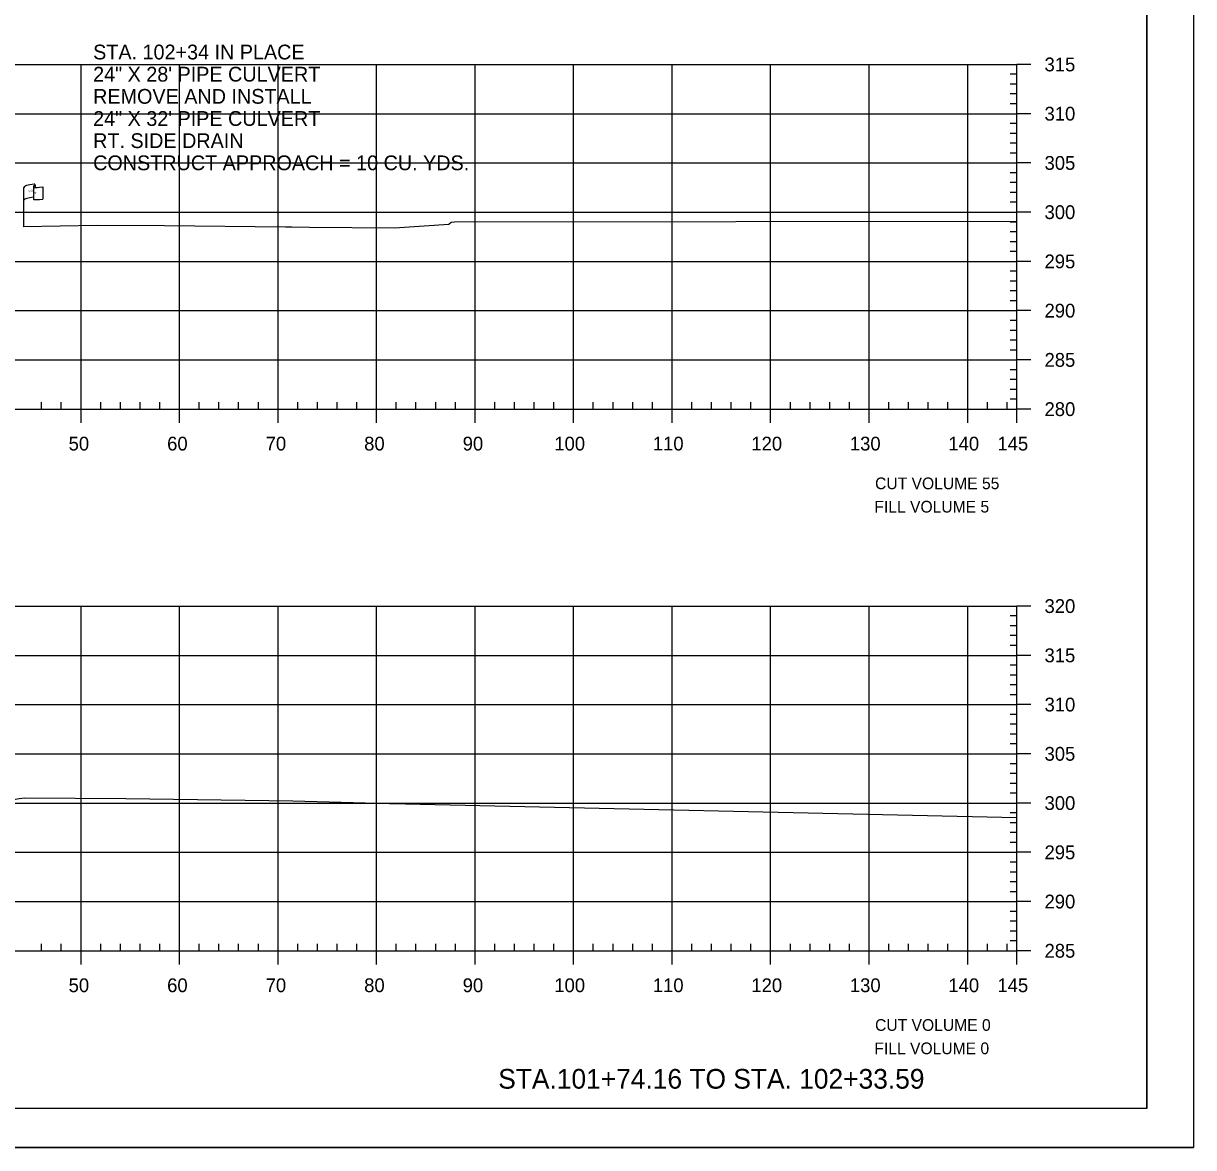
# Model space of a CAD drawing. Extents: x 1370843 to 1371177, y 380307 to 382654.
# Drawn here: x 1371057.9 to 1371176.6, y 380307.5 to 380421.6 of the extents above; entities that cross this region are included whole.
import ezdxf

# ---------------------------------------------------------------- set-up
doc = ezdxf.new("R2010")
doc.units = 0
for name, color, linetype in [('R_Axis', 7, 'Continuous'), ('R_Axis Annot', 7, 'Continuous'), ('R_Border', 7, 'Continuous'), ('R_Border Notes', 7, 'Continuous'), ('R_Draft', 7, 'Continuous'), ('R_Exist Surface', 7, 'Continuous'), ('R_Grid', 7, 'Continuous'), ('R_No Plot', 7, 'Continuous'), ('R_ROW', 7, 'Continuous'), ('R_Water Annot', 7, 'Continuous')]:
    doc.layers.add(name, color=color, linetype=linetype)

msp = doc.modelspace()

# ---------------------------------------------------------------- linework, layer by layer
at = {"layer": 'R_Axis'}
for p, q in [((1371158.71, 380382.45), (1371158.71, 380417.45)), ((1371160.11, 380417.45), (1371158.71, 380417.45)), ((1371158.71, 380416.45), (1371158.01, 380416.45)), ((1371158.71, 380415.45), (1371158.01, 380415.45)), ((1371158.71, 380414.45), (1371158.01, 380414.45)), ((1371158.71, 380413.45), (1371158.01, 380413.45)), ((1371160.11, 380412.45), (1371158.71, 380412.45)), ((1371158.71, 380411.45), (1371158.01, 380411.45)), ((1371158.71, 380410.45), (1371158.01, 380410.45)), ((1371158.71, 380409.45), (1371158.01, 380409.45)), ((1371158.71, 380408.45), (1371158.01, 380408.45)), ((1371160.11, 380407.45), (1371158.71, 380407.45)), ((1371158.71, 380406.45), (1371158.01, 380406.45)), ((1371158.71, 380405.45), (1371158.01, 380405.45)), ((1371158.71, 380404.45), (1371158.01, 380404.45)), ((1371158.71, 380403.45), (1371158.01, 380403.45)), ((1371160.11, 380402.45), (1371158.71, 380402.45)), ((1371158.71, 380401.45), (1371158.01, 380401.45)), ((1371158.71, 380400.45), (1371158.01, 380400.45)), ((1371158.71, 380399.45), (1371158.01, 380399.45)), ((1371158.71, 380398.45), (1371158.01, 380398.45)), ((1371160.11, 380397.45), (1371158.71, 380397.45)), ((1371158.71, 380396.45), (1371158.01, 380396.45)), ((1371158.71, 380395.45), (1371158.01, 380395.45)), ((1371158.71, 380394.45), (1371158.01, 380394.45)), ((1371158.71, 380393.45), (1371158.01, 380393.45)), ((1371160.11, 380392.45), (1371158.71, 380392.45)), ((1371158.71, 380391.45), (1371158.01, 380391.45)), ((1371158.71, 380390.45), (1371158.01, 380390.45)), ((1371158.71, 380389.45), (1371158.01, 380389.45)), ((1371158.71, 380388.45), (1371158.01, 380388.45)), ((1371160.11, 380387.45), (1371158.71, 380387.45)), ((1371158.71, 380386.45), (1371158.01, 380386.45)), ((1371158.71, 380385.45), (1371158.01, 380385.45)), ((1371158.71, 380384.45), (1371158.01, 380384.45)), ((1371059.71, 380382.45), (1371059.71, 380383.15)), ((1371061.71, 380382.45), (1371061.71, 380383.15)), ((1371065.71, 380382.45), (1371065.71, 380383.15)), ((1371067.71, 380382.45), (1371067.71, 380383.15)), ((1371069.71, 380382.45), (1371069.71, 380383.15)), ((1371071.71, 380382.45), (1371071.71, 380383.15)), ((1371075.71, 380382.45), (1371075.71, 380383.15)), ((1371077.71, 380382.45), (1371077.71, 380383.15)), ((1371079.71, 380382.45), (1371079.71, 380383.15)), ((1371081.71, 380382.45), (1371081.71, 380383.15)), ((1371085.71, 380382.45), (1371085.71, 380383.15)), ((1371087.71, 380382.45), (1371087.71, 380383.15)), ((1371089.71, 380382.45), (1371089.71, 380383.15)), ((1371091.71, 380382.45), (1371091.71, 380383.15)), ((1371095.71, 380382.45), (1371095.71, 380383.15)), ((1371097.71, 380382.45), (1371097.71, 380383.15)), ((1371099.71, 380382.45), (1371099.71, 380383.15)), ((1371101.71, 380382.45), (1371101.71, 380383.15)), ((1371105.71, 380382.45), (1371105.71, 380383.15)), ((1371107.71, 380382.45), (1371107.71, 380383.15)), ((1371109.71, 380382.45), (1371109.71, 380383.15)), ((1371111.71, 380382.45), (1371111.71, 380383.15)), ((1371115.71, 380382.45), (1371115.71, 380383.15)), ((1371117.71, 380382.45), (1371117.71, 380383.15)), ((1371119.71, 380382.45), (1371119.71, 380383.15)), ((1371121.71, 380382.45), (1371121.71, 380383.15)), ((1371125.71, 380382.45), (1371125.71, 380383.15)), ((1371127.71, 380382.45), (1371127.71, 380383.15)), ((1371129.71, 380382.45), (1371129.71, 380383.15)), ((1371131.71, 380382.45), (1371131.71, 380383.15)), ((1371135.71, 380382.45), (1371135.71, 380383.15)), ((1371137.71, 380382.45), (1371137.71, 380383.15)), ((1371139.71, 380382.45), (1371139.71, 380383.15)), ((1371141.71, 380382.45), (1371141.71, 380383.15)), ((1371145.71, 380382.45), (1371145.71, 380383.15)), ((1371147.71, 380382.45), (1371147.71, 380383.15)), ((1371149.71, 380382.45), (1371149.71, 380383.15)), ((1371151.71, 380382.45), (1371151.71, 380383.15)), ((1371155.71, 380382.45), (1371155.71, 380383.15)), ((1371157.71, 380382.45), (1371157.71, 380383.15)), ((1371158.71, 380383.45), (1371158.01, 380383.45)), ((1370868.71, 380382.45), (1371158.71, 380382.45)), ((1371063.71, 380381.05), (1371063.71, 380382.45)), ((1371073.71, 380381.05), (1371073.71, 380382.45)), ((1371083.71, 380381.05), (1371083.71, 380382.45)), ((1371093.71, 380381.05), (1371093.71, 380382.45)), ((1371103.71, 380381.05), (1371103.71, 380382.45)), ((1371113.71, 380381.05), (1371113.71, 380382.45)), ((1371123.71, 380381.05), (1371123.71, 380382.45)), ((1371133.71, 380381.05), (1371133.71, 380382.45)), ((1371143.71, 380381.05), (1371143.71, 380382.45)), ((1371153.71, 380381.05), (1371153.71, 380382.45)), ((1371158.71, 380381.05), (1371158.71, 380382.45)), ((1371160.11, 380382.45), (1371158.71, 380382.45)), ((1371158.71, 380327.45), (1371158.71, 380362.45)), ((1371160.11, 380362.45), (1371158.71, 380362.45)), ((1371158.71, 380361.45), (1371158.01, 380361.45)), ((1371158.71, 380360.45), (1371158.01, 380360.45)), ((1371158.71, 380359.45), (1371158.01, 380359.45)), ((1371158.71, 380358.45), (1371158.01, 380358.45)), ((1371160.11, 380357.45), (1371158.71, 380357.45)), ((1371158.71, 380356.45), (1371158.01, 380356.45)), ((1371158.71, 380355.45), (1371158.01, 380355.45)), ((1371158.71, 380354.45), (1371158.01, 380354.45)), ((1371158.71, 380353.45), (1371158.01, 380353.45)), ((1371160.11, 380352.45), (1371158.71, 380352.45)), ((1371158.71, 380351.45), (1371158.01, 380351.45)), ((1371158.71, 380350.45), (1371158.01, 380350.45)), ((1371158.71, 380349.45), (1371158.01, 380349.45)), ((1371158.71, 380348.45), (1371158.01, 380348.45)), ((1371160.11, 380347.45), (1371158.71, 380347.45)), ((1371158.71, 380346.45), (1371158.01, 380346.45)), ((1371158.71, 380345.45), (1371158.01, 380345.45)), ((1371158.71, 380344.45), (1371158.01, 380344.45)), ((1371158.71, 380343.45), (1371158.01, 380343.45)), ((1371158.71, 380341.45), (1371158.01, 380341.45)), ((1371160.11, 380342.45), (1371158.71, 380342.45)), ((1371158.71, 380340.45), (1371158.01, 380340.45)), ((1371158.71, 380339.45), (1371158.01, 380339.45)), ((1371158.71, 380338.45), (1371158.01, 380338.45)), ((1371160.11, 380337.45), (1371158.71, 380337.45)), ((1371158.71, 380336.45), (1371158.01, 380336.45)), ((1371158.71, 380335.45), (1371158.01, 380335.45)), ((1371158.71, 380334.45), (1371158.01, 380334.45)), ((1371158.71, 380333.45), (1371158.01, 380333.45)), ((1371160.11, 380332.45), (1371158.71, 380332.45)), ((1371158.71, 380331.45), (1371158.01, 380331.45)), ((1371158.71, 380330.45), (1371158.01, 380330.45)), ((1371158.71, 380329.45), (1371158.01, 380329.45)), ((1371158.71, 380328.45), (1371158.01, 380328.45)), ((1370868.71, 380327.45), (1371158.71, 380327.45)), ((1371059.71, 380327.45), (1371059.71, 380328.15)), ((1371061.71, 380327.45), (1371061.71, 380328.15)), ((1371063.71, 380326.05), (1371063.71, 380327.45)), ((1371065.71, 380327.45), (1371065.71, 380328.15)), ((1371067.71, 380327.45), (1371067.71, 380328.15)), ((1371069.71, 380327.45), (1371069.71, 380328.15)), ((1371071.71, 380327.45), (1371071.71, 380328.15)), ((1371073.71, 380326.05), (1371073.71, 380327.45)), ((1371075.71, 380327.45), (1371075.71, 380328.15)), ((1371077.71, 380327.45), (1371077.71, 380328.15)), ((1371079.71, 380327.45), (1371079.71, 380328.15)), ((1371081.71, 380327.45), (1371081.71, 380328.15)), ((1371083.71, 380326.05), (1371083.71, 380327.45)), ((1371085.71, 380327.45), (1371085.71, 380328.15)), ((1371087.71, 380327.45), (1371087.71, 380328.15)), ((1371089.71, 380327.45), (1371089.71, 380328.15)), ((1371091.71, 380327.45), (1371091.71, 380328.15)), ((1371093.71, 380326.05), (1371093.71, 380327.45)), ((1371095.71, 380327.45), (1371095.71, 380328.15)), ((1371097.71, 380327.45), (1371097.71, 380328.15)), ((1371099.71, 380327.45), (1371099.71, 380328.15)), ((1371101.71, 380327.45), (1371101.71, 380328.15)), ((1371103.71, 380326.05), (1371103.71, 380327.45)), ((1371105.71, 380327.45), (1371105.71, 380328.15)), ((1371107.71, 380327.45), (1371107.71, 380328.15)), ((1371109.71, 380327.45), (1371109.71, 380328.15)), ((1371111.71, 380327.45), (1371111.71, 380328.15)), ((1371113.71, 380326.05), (1371113.71, 380327.45)), ((1371115.71, 380327.45), (1371115.71, 380328.15)), ((1371117.71, 380327.45), (1371117.71, 380328.15)), ((1371119.71, 380327.45), (1371119.71, 380328.15)), ((1371121.71, 380327.45), (1371121.71, 380328.15)), ((1371123.71, 380326.05), (1371123.71, 380327.45)), ((1371125.71, 380327.45), (1371125.71, 380328.15)), ((1371127.71, 380327.45), (1371127.71, 380328.15)), ((1371129.71, 380327.45), (1371129.71, 380328.15)), ((1371131.71, 380327.45), (1371131.71, 380328.15)), ((1371133.71, 380326.05), (1371133.71, 380327.45)), ((1371135.71, 380327.45), (1371135.71, 380328.15)), ((1371137.71, 380327.45), (1371137.71, 380328.15)), ((1371139.71, 380327.45), (1371139.71, 380328.15)), ((1371141.71, 380327.45), (1371141.71, 380328.15)), ((1371143.71, 380326.05), (1371143.71, 380327.45)), ((1371145.71, 380327.45), (1371145.71, 380328.15)), ((1371147.71, 380327.45), (1371147.71, 380328.15)), ((1371149.71, 380327.45), (1371149.71, 380328.15)), ((1371151.71, 380327.45), (1371151.71, 380328.15)), ((1371153.71, 380326.05), (1371153.71, 380327.45)), ((1371155.71, 380327.45), (1371155.71, 380328.15)), ((1371157.71, 380327.45), (1371157.71, 380328.15)), ((1371158.71, 380326.05), (1371158.71, 380327.45)), ((1371160.11, 380327.45), (1371158.71, 380327.45))]:
    msp.add_line(p, q, dxfattribs=at)
at = {"layer": 'R_Border'}
for q in [(1371171.89, 380516.91), (1370855.71, 380311.45)]:
    msp.add_line((1371171.89, 380311.45), q, dxfattribs=at)
at = {"layer": 'R_Exist Surface'}
for p, q in [((1371101.63, 380401.47), (1371158.71, 380401.55)), ((1371095.13, 380342.39), (1371158.71, 380341))]:
    msp.add_line(p, q, dxfattribs=at)
for points in [[(1371057.84, 380401), (1371065.35, 380401.14), (1371072.18, 380401.1), (1371084.45, 380400.96), (1371085.1, 380400.96), (1371086.9, 380400.93), (1371095.53, 380400.85), (1371101.06, 380401.22), (1371101.28, 380401.43), (1371101.63, 380401.47)], [(1370939.13, 380344.35), (1370975.03, 380343.98), (1370982.17, 380341.27), (1370984.78, 380340.61), (1370986.66, 380341.35), (1370991.29, 380343.05), (1370993.11, 380343.35), (1371000.35, 380343.47), (1371027.08, 380343.09), (1371035.71, 380342.8), (1371035.99, 380342.72), (1371039.4, 380342.34), (1371044.83, 380341.28), (1371046.73, 380341.19), (1371048.66, 380341.34), (1371054.51, 380342.39), (1371057.43, 380342.9), (1371058.02, 380342.99), (1371068.25, 380342.93), (1371085.22, 380342.66), (1371095.01, 380342.39), (1371095.09, 380342.39), (1371095.13, 380342.39)]]:
    msp.add_lwpolyline(points, dxfattribs=at)
at = {"layer": 'R_Grid'}
for p, q in [((1370868.71, 380417.45), (1371158.71, 380417.45)), ((1371063.71, 380382.45), (1371063.71, 380417.45)), ((1371073.71, 380382.45), (1371073.71, 380417.45)), ((1371083.71, 380382.45), (1371083.71, 380417.45)), ((1371093.71, 380382.45), (1371093.71, 380417.45)), ((1371103.71, 380382.45), (1371103.71, 380417.45)), ((1371113.71, 380382.45), (1371113.71, 380417.45)), ((1371123.71, 380382.45), (1371123.71, 380417.45)), ((1371133.71, 380382.45), (1371133.71, 380417.45)), ((1371143.71, 380382.45), (1371143.71, 380417.45)), ((1371153.71, 380382.45), (1371153.71, 380417.45)), ((1371158.71, 380382.45), (1371158.71, 380417.45)), ((1370868.71, 380412.45), (1371158.71, 380412.45)), ((1370868.71, 380407.45), (1371158.71, 380407.45)), ((1370868.71, 380402.45), (1371158.71, 380402.45)), ((1370868.71, 380397.45), (1371158.71, 380397.45)), ((1370868.71, 380392.45), (1371158.71, 380392.45)), ((1370868.71, 380387.45), (1371158.71, 380387.45)), ((1370868.71, 380382.45), (1371158.71, 380382.45)), ((1370868.71, 380362.45), (1371158.71, 380362.45)), ((1371063.71, 380327.45), (1371063.71, 380362.45)), ((1371073.71, 380327.45), (1371073.71, 380362.45)), ((1371083.71, 380327.45), (1371083.71, 380362.45)), ((1371093.71, 380327.45), (1371093.71, 380362.45)), ((1371103.71, 380327.45), (1371103.71, 380362.45)), ((1371113.71, 380327.45), (1371113.71, 380362.45)), ((1371123.71, 380327.45), (1371123.71, 380362.45)), ((1371133.71, 380327.45), (1371133.71, 380362.45)), ((1371143.71, 380327.45), (1371143.71, 380362.45)), ((1371153.71, 380327.45), (1371153.71, 380362.45)), ((1371158.71, 380327.45), (1371158.71, 380362.45)), ((1370868.71, 380357.45), (1371158.71, 380357.45)), ((1370868.71, 380352.45), (1371158.71, 380352.45)), ((1370868.71, 380347.45), (1371158.71, 380347.45)), ((1370868.71, 380342.45), (1371158.71, 380342.45)), ((1370868.71, 380337.45), (1371158.71, 380337.45)), ((1370868.71, 380332.45), (1371158.71, 380332.45)), ((1370868.71, 380327.45), (1371158.71, 380327.45))]:
    msp.add_line(p, q, dxfattribs=at)
at = {"layer": 'R_No Plot'}
msp.add_line((1370843.31, 380307.47), (1371176.64, 380307.47), dxfattribs=at)
for points in [[(1370843.3, 380520.8), (1371176.64, 380520.8), (1371176.64, 380307.47), (1370843.3, 380307.47)], [(1371089.63, 380516.91), (1371089.63, 380507.03), (1371125.36, 380507.03), (1371125.36, 380504.11), (1371148.56, 380504.11), (1371148.56, 380479.78), (1371171.89, 380479.78), (1371171.89, 380311.45), (1370855.71, 380311.45), (1370855.71, 380516.91)]]:
    msp.add_lwpolyline(points, close=True, dxfattribs=at)
at = {"layer": 'R_ROW'}
for p, q in [((1371057.89, 380401), (1371057.89, 380404.95)), ((1371058.88, 380405.05), (1371058.88, 380405.04)), ((1371058.88, 380405.04), (1371058.88, 380403.81)), ((1371059.05, 380405.21), (1371059.05, 380404.96)), ((1371059.82, 380405.01), (1371059.82, 380403.77))]:
    msp.add_line(p, q, dxfattribs=at)
for centre, radius, start, end in [((1371058.96, 380405.05), 0.078, 88.6458, 274.2828), ((1371058.97, 380405.21), 0.0783, 263.0712, 93.9564), ((1371058.96, 380403.81), 0.0783, 180, 273.9564)]:
    msp.add_arc(centre, radius, start, end, dxfattribs=at)
for centre, major_axis, ratio, start_param, end_param in [((1371059.47, 380405), (-1.58, -0.04), 0.19887, 5.030368, 6.283185), ((1371060.18, 380405.11), (-1.23, -0.13), 0.052933, 0.159456, 1.268315), ((1371059.47, 380403.68), (-1.58, -0.04), 0.19887, 5.083035, 6.194897), ((1371060.18, 380403.87), (-1.23, -0.13), 0.052933, 0.159456, 1.268315)]:
    msp.add_ellipse(centre, major_axis=major_axis, ratio=ratio, start_param=start_param, end_param=end_param, dxfattribs=at)

# ---------------------------------------------------------------- texts
at = {"layer": 'R_Axis Annot'}
for s, p in [('315', (1371161.51, 380416.75)), ('310', (1371161.51, 380411.75)), ('305', (1371161.51, 380406.75)), ('300', (1371161.51, 380401.75)), ('295', (1371161.51, 380396.75)), ('290', (1371161.51, 380391.75)), ('285', (1371161.51, 380386.75)), ('280', (1371161.51, 380381.75)), ('50', (1371062.45, 380378.25)), ('60', (1371072.45, 380378.25)), ('70', (1371082.45, 380378.25)), ('80', (1371092.45, 380378.25)), ('90', (1371102.45, 380378.25)), ('100', (1371111.75, 380378.25)), ('110', (1371121.75, 380378.25)), ('120', (1371131.75, 380378.25)), ('130', (1371141.75, 380378.25)), ('140', (1371151.75, 380378.25)), ('145', (1371156.73, 380378.25)), ('320', (1371161.51, 380361.75)), ('315', (1371161.51, 380356.75)), ('310', (1371161.51, 380351.75)), ('305', (1371161.51, 380346.75)), ('300', (1371161.51, 380341.75)), ('295', (1371161.51, 380336.75)), ('290', (1371161.51, 380331.75)), ('285', (1371161.51, 380326.75)), ('50', (1371062.45, 380323.25)), ('60', (1371072.45, 380323.25)), ('70', (1371082.45, 380323.25)), ('80', (1371092.45, 380323.25)), ('90', (1371102.45, 380323.25)), ('100', (1371111.75, 380323.25)), ('110', (1371121.75, 380323.25)), ('120', (1371131.75, 380323.25)), ('130', (1371141.75, 380323.25)), ('140', (1371151.75, 380323.25)), ('145', (1371156.73, 380323.25))]:
    msp.add_text(s, height=1.4, dxfattribs=at).set_placement(p)
at = {"layer": 'R_Border Notes'}
for s, p in [('CUT VOLUME 55', (1371144.31, 380374.32)), ('FILL VOLUME 5', (1371144.24, 380371.95)), ('CUT VOLUME 0', (1371144.31, 380319.32)), ('FILL VOLUME 0', (1371144.24, 380316.95))]:
    msp.add_text(s, height=1.1875, dxfattribs=at).set_placement(p)
at = {"layer": 'R_Draft'}
msp.add_text('STA.101+74.16 TO STA. 102+33.59', height=2, dxfattribs=at).set_placement((1371106.06, 380313.45))
at = {"layer": 'R_ROW'}
for s, height, rotation, p in [('R ', 0.2, 9.9884, (1371058.41, 380404.46)), (' O', 0.2, 9.9884, (1371058.55, 380404.5)), ('W', 0.2, 351.1788, (1371058.88, 380404.33)), ('DWB 11-9-07', 0.001, 90, (1371059.05, 380404.96)), ('DWB 11-9-07', 0.001, 5.0717, (1371059.81, 380403.77)), ('DWB 11-9-07', 0.001, 90, (1371057.89, 380401))]:
    msp.add_text(s, height=height, rotation=rotation, dxfattribs=at).set_placement(p)
at = {"layer": 'R_Water Annot'}
for s, p in [('STA. 102+34 IN PLACE', (1371064.94, 380417.96)), ('24" X 28\' PIPE CULVERT', (1371064.94, 380415.71)), ('REMOVE AND INSTALL', (1371064.94, 380413.46)), ('24" X 32\' PIPE CULVERT', (1371064.94, 380411.21)), ('RT. SIDE DRAIN', (1371064.94, 380408.96)), ('CONSTRUCT APPROACH = 10 CU. YDS.', (1371064.94, 380406.71))]:
    msp.add_text(s, height=1.5, dxfattribs=at).set_placement(p)

doc.saveas('drawing.dxf')
